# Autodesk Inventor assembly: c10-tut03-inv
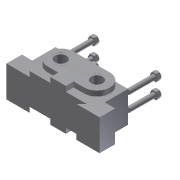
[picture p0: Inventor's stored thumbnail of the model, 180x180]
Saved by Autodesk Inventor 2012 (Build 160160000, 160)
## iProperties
Created: 2009-05
Part Number: c10-tut03-inv
Document SubType Name: Assembly
Designer: Sham
Author: Sham
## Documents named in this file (5)
- C:\Users\CadCim\Documents\SAILESH\NEW Menuscript\c10\tUT03\c10-tut03-inv.iam
- C:\Users\CadCim\Documents\SAILESH\NEW Menuscript\PART FILES-2012 Inv\faculty\c10-inv-2012-prt\Tutorials\c10-tut03-inv\base.ipt
- C:\Users\CadCim\Documents\SAILESH\NEW Menuscript\PART FILES-2012 Inv\faculty\c10-inv-2012-prt\Tutorials\c10-tut03-inv\cap.ipt
- C:\Users\CadCim\Documents\SAILESH\NEW Menuscript\PART FILES-2012 Inv\faculty\c10-inv-2012-prt\Tutorials\c10-tut03-inv\bolt.ipt
- C:\Users\CadCim\Documents\SAILESH\NEW Menuscript\PART FILES-2012 Inv\faculty\c10-inv-2012-prt\Tutorials\c10-tut03-inv\bushing.ipt
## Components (10 placed, 4 different names)
1. base:1 — Mate:1, Mate:2, Mate:3, Insert:3, Insert:4
2. cap:1 — Mate:1, Mate:2, Mate:3, Insert:1, Insert:2
3. bushing:2 — Insert:3
4. bushing:3 — Insert:4
5. bolt:1 — Insert:1
6. bolt:6
7. bolt:7
8. bolt:8
9. bolt:5 — Insert:2
10. bolt:9
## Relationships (7: Insert 4, Mate 3)
- Mate:1: base:1 ↔ cap:1
- Mate:2: base:1 ↔ cap:1
- Mate:3: base:1 ↔ cap:1
- Insert:1: cap:1 ↔ bolt:1
- Insert:2: cap:1 ↔ bolt:5
- Insert:3: base:1 ↔ bushing:2
- Insert:4: base:1 ↔ bushing:3
